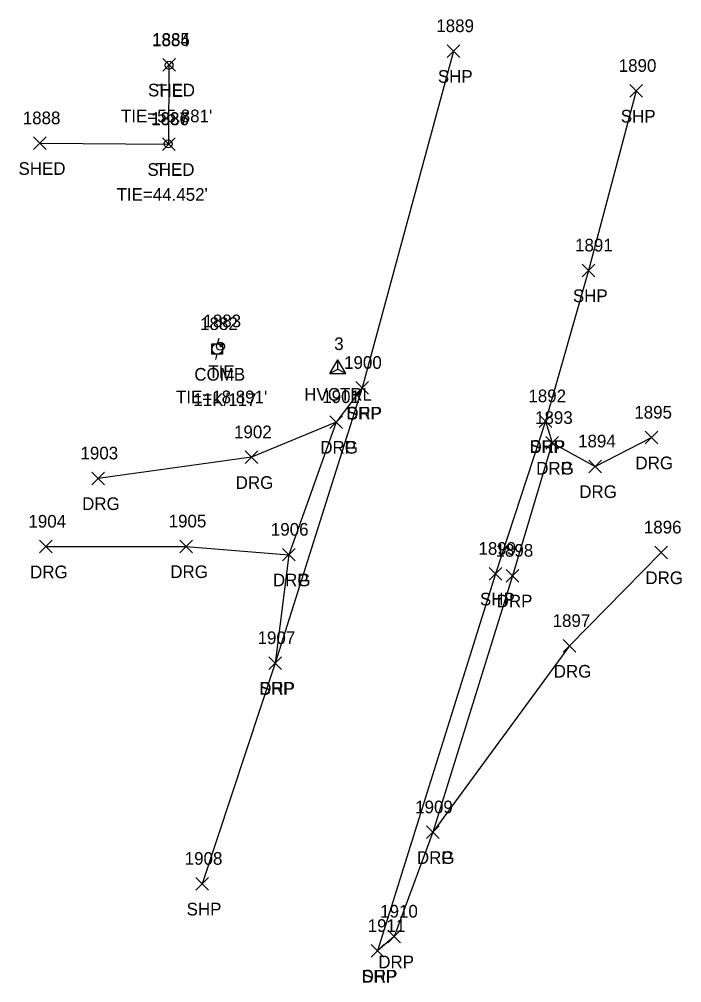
# Model space of a CAD drawing. Extents: x 1554917 to 1555870, y 813367 to 816333.
# Drawn here: x 1555427.7 to 1555532.3, y 814662.1 to 814814.3 of the extents above; entities that cross this region are included whole.
import ezdxf

# ---------------------------------------------------------------- set-up
doc = ezdxf.new("R2010")
doc.units = 0
for name, color, linetype in [('C_A', 7, 'Continuous'), ('C_C', 7, 'Continuous'), ('C_I', 7, 'Continuous'), ('CBP', 7, 'Continuous'), ('CPSM', 7, 'Continuous'), ('L_A', 7, 'Continuous'), ('L_I', 7, 'Continuous'), ('L_TIC', 7, 'Continuous'), ('LBC', 7, 'Continuous'), ('P_A', 7, 'Continuous'), ('P_I', 7, 'Continuous'), ('P_TIC', 7, 'Continuous'), ('PSP', 7, 'Continuous'), ('R_A', 7, 'Continuous'), ('R_I', 7, 'Continuous'), ('R_TIC', 7, 'Continuous'), ('RDG', 7, 'Continuous'), ('RDP', 7, 'Continuous'), ('U_A', 7, 'Continuous'), ('U_C', 7, 'Continuous'), ('U_I', 7, 'Continuous'), ('UP', 7, 'Continuous')]:
    doc.layers.add(name, color=color, linetype=linetype)

msp = doc.modelspace()

# ---------------------------------------------------------------- linework, layer by layer
at = {"layer": 'CBP'}
for centre, radius in [((1555451.33, 814807), 0.625), ((1555451.33, 814807), 0.0833), ((1555451.19, 814794.59), 0.625), ((1555451.19, 814794.59), 0.0833), ((1555459.45, 814762.62), 0.625), ((1555459.45, 814762.62), 0.0833)]:
    msp.add_circle(centre, radius, dxfattribs=at)
at = {"layer": 'CPSM'}
for p, q in [((1555476.75, 814758.3), (1555478, 814760.46)), ((1555479.25, 814758.3), (1555478, 814760.46)), ((1555478, 814759.02), (1555478, 814760.46)), ((1555476.75, 814758.3), (1555478, 814759.02)), ((1555476.75, 814758.3), (1555479.25, 814758.3)), ((1555478, 814759.02), (1555478, 814759.02)), ((1555478, 814759.02), (1555479.25, 814758.3))]:
    msp.add_line(p, q, dxfattribs=at)
at = {"layer": 'L_TIC'}
for points in [[(1555450.36, 814806.08), (1555452.36, 814808.08)], [(1555452.36, 814806.08), (1555450.36, 814808.08)], [(1555429.91, 814793.69), (1555431.91, 814795.69)], [(1555431.91, 814793.69), (1555429.91, 814795.69)], [(1555450.28, 814793.53), (1555452.28, 814795.53)], [(1555452.28, 814793.53), (1555450.28, 814795.53)]]:
    msp.add_lwpolyline(points, dxfattribs=at)
at = {"layer": 'LBC'}
for p, q in [((1555451.28, 814794.53), (1555451.36, 814807.08)), ((1555430.91, 814794.69), (1555451.28, 814794.53))]:
    msp.add_line(p, q, dxfattribs=at)
at = {"layer": 'P_TIC'}
for points in [[(1555495.26, 814808.24), (1555497.26, 814810.24)], [(1555497.26, 814808.24), (1555495.26, 814810.24)], [(1555524.16, 814801.96), (1555526.16, 814803.96)], [(1555526.16, 814801.96), (1555524.16, 814803.96)], [(1555516.6, 814773.59), (1555518.6, 814775.59)], [(1555518.6, 814773.59), (1555516.6, 814775.59)], [(1555480.85, 814755.05), (1555482.85, 814757.05)], [(1555482.85, 814755.05), (1555480.85, 814757.05)], [(1555509.8, 814749.78), (1555511.8, 814751.78)], [(1555511.8, 814749.78), (1555509.8, 814751.78)], [(1555501.92, 814725.68), (1555503.92, 814727.68)], [(1555503.92, 814725.68), (1555501.92, 814727.68)], [(1555467.1, 814711.58), (1555469.1, 814713.58)], [(1555469.1, 814711.58), (1555467.1, 814713.58)], [(1555455.58, 814676.72), (1555457.58, 814678.72)], [(1555457.58, 814676.72), (1555455.58, 814678.72)], [(1555483.28, 814666.12), (1555485.28, 814668.12)], [(1555485.28, 814666.12), (1555483.28, 814668.12)]]:
    msp.add_lwpolyline(points, dxfattribs=at)
at = {"layer": 'PSP'}
for points in [[(1555496.26, 814809.24), (1555481.85, 814756.05), (1555468.1, 814712.58), (1555456.58, 814677.72)], [(1555525.16, 814802.96), (1555517.6, 814774.59), (1555510.8, 814750.78), (1555502.92, 814726.68), (1555484.28, 814667.12)]]:
    msp.add_lwpolyline(points, dxfattribs=at)
at = {"layer": 'R_TIC'}
for points in [[(1555480.85, 814755.05), (1555482.85, 814757.05)], [(1555482.85, 814755.05), (1555480.85, 814757.05)], [(1555476.75, 814749.65), (1555478.75, 814751.65)], [(1555478.75, 814749.65), (1555476.75, 814751.65)], [(1555476.75, 814749.65), (1555478.75, 814751.65)], [(1555478.75, 814749.65), (1555476.75, 814751.65)], [(1555509.8, 814749.78), (1555511.8, 814751.78)], [(1555511.8, 814749.78), (1555509.8, 814751.78)], [(1555526.54, 814747.19), (1555528.54, 814749.19)], [(1555528.54, 814747.19), (1555526.54, 814749.19)], [(1555510.85, 814746.35), (1555512.85, 814748.35)], [(1555512.85, 814746.35), (1555510.85, 814748.35)], [(1555510.85, 814746.35), (1555512.85, 814748.35)], [(1555512.85, 814746.35), (1555510.85, 814748.35)], [(1555463.37, 814744.09), (1555465.37, 814746.09)], [(1555465.37, 814744.09), (1555463.37, 814746.09)], [(1555517.65, 814742.65), (1555519.65, 814744.65)], [(1555519.65, 814742.65), (1555517.65, 814744.65)], [(1555439.11, 814740.75), (1555441.11, 814742.75)], [(1555441.11, 814740.75), (1555439.11, 814742.75)], [(1555430.89, 814729.97), (1555432.89, 814731.97)], [(1555432.89, 814729.97), (1555430.89, 814731.97)], [(1555453.04, 814730.01), (1555455.04, 814732.01)], [(1555455.04, 814730.01), (1555453.04, 814732.01)], [(1555528.1, 814729.05), (1555530.1, 814731.05)], [(1555530.1, 814729.05), (1555528.1, 814731.05)], [(1555469.25, 814728.7), (1555471.25, 814730.7)], [(1555471.25, 814728.7), (1555469.25, 814730.7)], [(1555469.25, 814728.7), (1555471.25, 814730.7)], [(1555471.25, 814728.7), (1555469.25, 814730.7)], [(1555504.62, 814725.38), (1555506.62, 814727.38)], [(1555506.62, 814725.38), (1555504.62, 814727.38)], [(1555513.62, 814714.28), (1555515.62, 814716.28)], [(1555515.62, 814714.28), (1555513.62, 814716.28)], [(1555467.1, 814711.58), (1555469.1, 814713.58)], [(1555469.1, 814711.58), (1555467.1, 814713.58)], [(1555492, 814684.85), (1555494, 814686.85)], [(1555494, 814684.85), (1555492, 814686.85)], [(1555492, 814684.85), (1555494, 814686.85)], [(1555494, 814684.85), (1555492, 814686.85)], [(1555485.9, 814668.38), (1555487.9, 814670.38)], [(1555487.9, 814668.38), (1555485.9, 814670.38)], [(1555483.28, 814666.12), (1555485.28, 814668.12)], [(1555485.28, 814666.12), (1555483.28, 814668.12)]]:
    msp.add_lwpolyline(points, dxfattribs=at)
at = {"layer": 'RDG'}
for points in [[(1555477.75, 814750.65), (1555464.37, 814745.09), (1555440.11, 814741.75)], [(1555511.85, 814747.35), (1555518.65, 814743.65), (1555527.54, 814748.19)], [(1555431.89, 814730.97), (1555454.04, 814731.01), (1555470.25, 814729.7)], [(1555529.1, 814730.05), (1555514.62, 814715.28), (1555493, 814685.85)]]:
    msp.add_lwpolyline(points, dxfattribs=at)
at = {"layer": 'RDP'}
for points in [[(1555481.85, 814756.05), (1555477.75, 814750.65), (1555470.25, 814729.7), (1555468.1, 814712.58)], [(1555510.8, 814750.78), (1555511.85, 814747.35), (1555505.62, 814726.38), (1555493, 814685.85), (1555486.9, 814669.38), (1555484.28, 814667.12)]]:
    msp.add_lwpolyline(points, dxfattribs=at)
at = {"layer": 'UP'}
for p, q in [((1555458.11, 814761.36), (1555458.11, 814763.02)), ((1555458.11, 814763.02), (1555459.78, 814763.02)), ((1555459.2, 814763.86), (1555458.95, 814763.02)), ((1555459.78, 814763.02), (1555459.78, 814761.36)), ((1555459.78, 814761.36), (1555458.11, 814761.36)), ((1555458.7, 814760.52), (1555458.95, 814761.36)), ((1555458.95, 814762.19), (1555458.95, 814762.19))]:
    msp.add_line(p, q, dxfattribs=at)
msp.add_circle((1555458.95, 814762.19), 0.833, dxfattribs=at)

# ---------------------------------------------------------------- texts
at = {"layer": 'C_A'}
for s, p in [('TIE', (1555449.41, 814802)), ('TIE', (1555449.27, 814789.59)), ('TIE', (1555457.53, 814757.62)), ('HVCTRL', (1555472.69, 814754.02))]:
    msp.add_text(s, height=2, dxfattribs=at).set_placement(p)
at = {"layer": 'C_C'}
for s, p in [("TIE=55.881'", (1555443.74, 814798)), ("TIE=44.452'", (1555443.04, 814785.59)), ("TIE=18.891'", (1555452.43, 814753.62))]:
    msp.add_text(s, height=2, dxfattribs=at).set_placement(p)
at = {"layer": 'C_I'}
for s, p in [('1884', (1555448.64, 814810)), ('1887', (1555448.5, 814797.59)), ('1883', (1555456.76, 814765.62)), ('3', (1555477.43, 814762.02))]:
    msp.add_text(s, height=2, dxfattribs=at).set_placement(p)
at = {"layer": 'L_A'}
for p in [(1555448, 814802.08), (1555427.55, 814789.69), (1555447.92, 814789.53)]:
    msp.add_text('SHED', height=2, dxfattribs=at).set_placement(p)
at = {"layer": 'L_I'}
for s, p in [('1885', (1555448.67, 814810.08)), ('1888', (1555428.22, 814797.69)), ('1886', (1555448.53, 814797.53))]:
    msp.add_text(s, height=2, dxfattribs=at).set_placement(p)
at = {"layer": 'P_A'}
for p in [(1555493.8, 814804.24), (1555522.7, 814797.96), (1555515.14, 814769.59), (1555479.39, 814751.05), (1555508.34, 814745.78), (1555500.46, 814721.68), (1555465.63, 814707.58), (1555454.11, 814672.72), (1555481.81, 814662.12)]:
    msp.add_text('SHP', height=2, dxfattribs=at).set_placement(p)
at = {"layer": 'P_I'}
for s, p in [('1889', (1555493.56, 814812.24)), ('1890', (1555522.38, 814805.96)), ('1891', (1555515.48, 814777.59)), ('1900', (1555478.99, 814759.05)), ('1892', (1555508.11, 814753.78)), ('1899', (1555500.22, 814729.68)), ('1907', (1555465.32, 814715.58)), ('1908', (1555453.81, 814680.72)), ('1911', (1555482.72, 814670.12))]:
    msp.add_text(s, height=2, dxfattribs=at).set_placement(p)
at = {"layer": 'R_A'}
for s, p in [('DRP', (1555479.34, 814751.05)), ('DRG', (1555475.23, 814745.65)), ('DRP', (1555475.23, 814745.65)), ('DRP', (1555508.29, 814745.78)), ('DRG', (1555525.02, 814743.19)), ('DRG', (1555509.34, 814742.35)), ('DRP', (1555509.34, 814742.35)), ('DRG', (1555461.86, 814740.09)), ('DRG', (1555516.14, 814738.65)), ('DRG', (1555437.6, 814736.75)), ('DRG', (1555429.38, 814725.97)), ('DRG', (1555451.53, 814726.01)), ('DRG', (1555467.74, 814724.7)), ('DRP', (1555467.74, 814724.7)), ('DRG', (1555526.59, 814725.05)), ('DRP', (1555503.1, 814721.38)), ('DRG', (1555512.11, 814710.28)), ('DRP', (1555465.58, 814707.58)), ('DRG', (1555490.49, 814680.85)), ('DRP', (1555490.49, 814680.85)), ('DRP', (1555484.39, 814664.38)), ('DRP', (1555481.77, 814662.12))]:
    msp.add_text(s, height=2, dxfattribs=at).set_placement(p)
at = {"layer": 'R_I'}
for s, p in [('1900', (1555478.99, 814759.05)), ('1901', (1555475.54, 814753.65)), ('1901', (1555475.54, 814753.65)), ('1892', (1555508.11, 814753.78)), ('1893', (1555509.16, 814750.35)), ('1893', (1555509.16, 814750.35)), ('1895', (1555524.84, 814751.19)), ('1902', (1555461.6, 814748.09)), ('1894', (1555515.96, 814746.65)), ('1903', (1555437.34, 814744.75)), ('1904', (1555429.12, 814733.97)), ('1905', (1555451.27, 814734.01)), ('1906', (1555467.42, 814732.7)), ('1906', (1555467.42, 814732.7)), ('1896', (1555526.35, 814733.05)), ('1898', (1555502.92, 814729.38)), ('1897', (1555511.93, 814718.28)), ('1907', (1555465.32, 814715.58)), ('1909', (1555490.22, 814688.85)), ('1909', (1555490.22, 814688.85)), ('1910', (1555484.69, 814672.38)), ('1911', (1555482.72, 814670.12))]:
    msp.add_text(s, height=2, dxfattribs=at).set_placement(p)
at = {"layer": 'U_A'}
msp.add_text('COMB', height=2, dxfattribs=at).set_placement((1555455.33, 814757.19))
at = {"layer": 'U_C'}
msp.add_text('11K/117', height=2, dxfattribs=at).set_placement((1555455.18, 814753.19))
at = {"layer": 'U_I'}
msp.add_text('1882', height=2, dxfattribs=at).set_placement((1555456.25, 814765.19))

doc.saveas('drawing.dxf')
